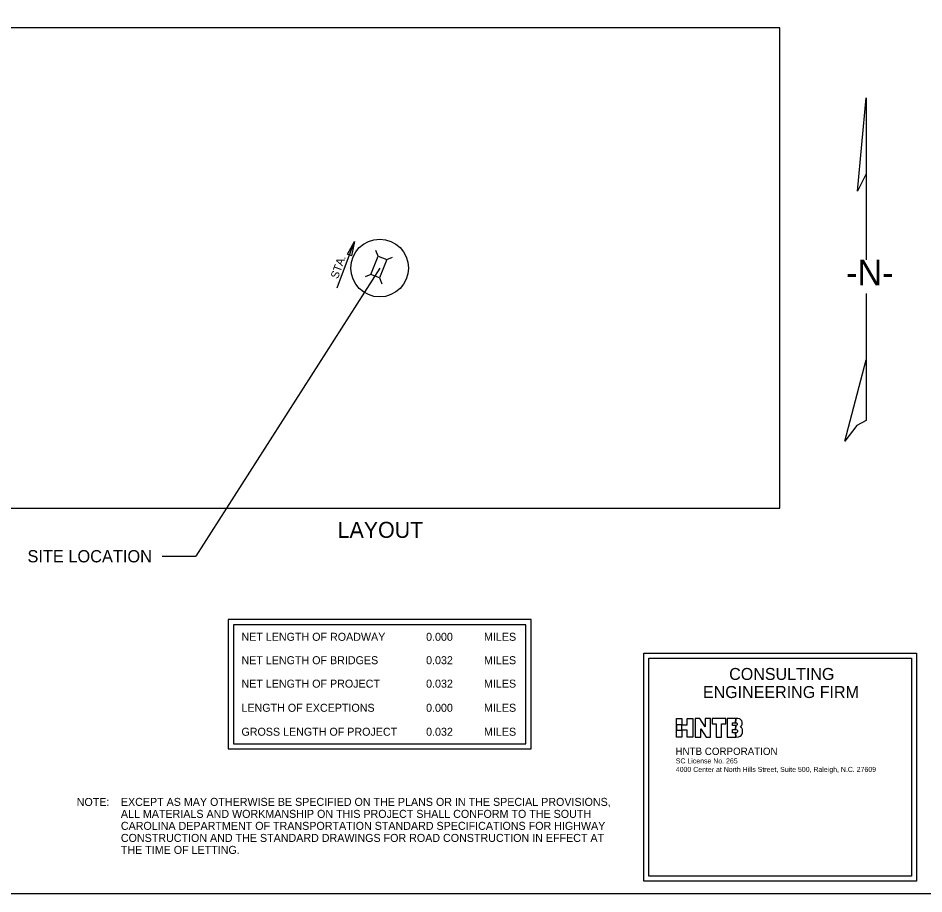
# Model space of a CAD drawing. Extents: x 0 to 4.05, y 0.02 to 4.32.
# Drawn here: x 1.008 to 2.188, y 0.042 to 1.182 of the extents above; entities that cross this region are included whole.
import ezdxf

# ---------------------------------------------------------------- set-up
doc = ezdxf.new("R2010")
doc.units = 0
for name, color, linetype in [('BR_AUTO DIMENSION', 7, 'Continuous'), ('BR_BORDER LINES', 7, 'Continuous'), ('BR_DETAILS', 7, 'Continuous'), ('BR_TEXT', 7, 'Continuous'), ('Default', 7, 'Continuous'), ('V7_23', 7, 'Continuous')]:
    doc.layers.add(name, color=color, linetype=linetype)

msp = doc.modelspace()

# ---------------------------------------------------------------- linework, layer by layer
at = {"layer": 'BR_AUTO DIMENSION'}
for p in [(1.4792, 0.8563), (1.1961, 0.4811)]:
    msp.add_line(p, (1.2399, 0.4811), dxfattribs=at)
msp.add_circle((1.4792, 0.8563), 0.0376, dxfattribs=at)
at = {"layer": 'BR_BORDER LINES'}
for points in [[(0.1667, 1.7917), (2.7917, 1.7917), (2.7917, 0.0417), (0.1667, 0.0417)], [(0.9583, 0.5438), (2, 0.5438), (2, 1.1688), (0.9583, 1.1688)]]:
    msp.add_lwpolyline(points, close=True, dxfattribs=at)
at = {"layer": 'BR_DETAILS'}
for p, q in [((1.8232, 0.3551), (2.1782, 0.3551)), ((1.8232, 0.0584), (1.8232, 0.3551)), ((2.1782, 0.3551), (2.1782, 0.0584)), ((1.8296, 0.3487), (2.1718, 0.3487)), ((1.8296, 0.0648), (1.8296, 0.3487)), ((2.1718, 0.3487), (2.1718, 0.0648)), ((2.1718, 0.0648), (1.8296, 0.0648)), ((2.1782, 0.0584), (1.8232, 0.0584))]:
    msp.add_line(p, q, dxfattribs=at)
at = {"layer": 'BR_TEXT'}
for p, q in [((1.4239, 0.8306), (1.4463, 0.8909)), ((1.4772, 0.8718), (1.4742, 0.8793)), ((1.4886, 0.8672), (1.496, 0.8706)), ((1.4676, 0.848), (1.4602, 0.8447)), ((1.479, 0.8434), (1.4821, 0.8359))]:
    msp.add_line(p, q, dxfattribs=at)
for points in [[(1.4372, 0.8743), (1.4463, 0.8909), (1.4424, 0.8724)], [(1.4772, 0.8718), (1.4886, 0.8672), (1.479, 0.8434), (1.4676, 0.848)], [(1.6763, 0.3987), (1.282, 0.3987), (1.282, 0.2303), (1.6763, 0.2303)], [(1.6696, 0.392), (1.2887, 0.392), (1.2887, 0.237), (1.6696, 0.237)]]:
    msp.add_lwpolyline(points, close=True, dxfattribs=at)
at = {"layer": 'Default'}
for p, q in [((2.1013, 0.9564), (2.1124, 1.0778)), ((2.1124, 1.0778), (2.1124, 0.979)), ((2.1124, 0.979), (2.1013, 0.9564)), ((2.1124, 0.979), (2.1124, 0.9105)), ((2.1124, 0.9105), (2.1124, 0.8668)), ((2.1124, 0.8232), (2.1124, 0.7369)), ((2.0849, 0.6311), (2.1124, 0.7369)), ((2.1124, 0.7369), (2.1124, 0.7238)), ((2.1124, 0.7238), (2.1124, 0.6577))]:
    msp.add_line(p, q, dxfattribs=at)
msp.add_lwpolyline([(2.1124, 0.6577), (2.1006, 0.6512), (2.0849, 0.6311)], dxfattribs=at)
at = {"layer": 'V7_23'}
for p, q in [((1.8655, 0.2458), (1.8655, 0.2698)), ((1.8655, 0.2698), (1.8726, 0.2698)), ((1.8726, 0.2617), (1.8658, 0.2617)), ((1.8658, 0.2617), (1.8658, 0.2546)), ((1.8726, 0.2698), (1.8726, 0.2617)), ((1.8726, 0.2546), (1.8726, 0.2617)), ((1.8726, 0.2617), (1.8797, 0.2617)), ((1.8797, 0.2617), (1.8797, 0.2698)), ((1.8797, 0.2698), (1.8868, 0.2698)), ((1.8868, 0.2698), (1.8868, 0.2458)), ((1.8959, 0.2698), (1.8901, 0.2698)), ((1.8901, 0.2698), (1.8901, 0.2458)), ((1.903, 0.2593), (1.8959, 0.2698)), ((1.91, 0.2698), (1.903, 0.2698)), ((1.903, 0.2698), (1.903, 0.2593)), ((1.91, 0.2458), (1.91, 0.2698)), ((1.912, 0.2698), (1.912, 0.2629)), ((1.9297, 0.2698), (1.912, 0.2698)), ((1.912, 0.2629), (1.9173, 0.2629)), ((1.9173, 0.2629), (1.9173, 0.2458)), ((1.9244, 0.2458), (1.9244, 0.2629)), ((1.9244, 0.2629), (1.9297, 0.2629)), ((1.9297, 0.2629), (1.9297, 0.2698)), ((1.9429, 0.2698), (1.9318, 0.2698)), ((1.9318, 0.2698), (1.9318, 0.2458)), ((1.9384, 0.2609), (1.9384, 0.2645)), ((1.9384, 0.2645), (1.9425, 0.2645)), ((1.9427, 0.2609), (1.9384, 0.2609)), ((1.9424, 0.2556), (1.9427, 0.2609)), ((1.9427, 0.2609), (1.9424, 0.2556)), ((1.9425, 0.2645), (1.9429, 0.2698)), ((1.9429, 0.2698), (1.9425, 0.2645)), ((1.8658, 0.2546), (1.8726, 0.2546)), ((1.8797, 0.2546), (1.8726, 0.2546)), ((1.8726, 0.2546), (1.8726, 0.2458)), ((1.8797, 0.2458), (1.8797, 0.2546)), ((1.8971, 0.2458), (1.8971, 0.2566)), ((1.8971, 0.2566), (1.9044, 0.2458)), ((1.9384, 0.2512), (1.9384, 0.2556)), ((1.9384, 0.2556), (1.9424, 0.2556)), ((1.9425, 0.2512), (1.9384, 0.2512)), ((1.9428, 0.2458), (1.9425, 0.2512)), ((1.9425, 0.2512), (1.9428, 0.2458)), ((1.8726, 0.2458), (1.8655, 0.2458)), ((1.8868, 0.2458), (1.8797, 0.2458)), ((1.8901, 0.2458), (1.8971, 0.2458)), ((1.9044, 0.2458), (1.91, 0.2458)), ((1.9173, 0.2458), (1.9244, 0.2458)), ((1.9318, 0.2458), (1.9428, 0.2458))]:
    msp.add_line(p, q, dxfattribs=at)
for points in [[(1.9425, 0.2645), (1.9444, 0.2645), (1.9446, 0.2632), (1.9446, 0.2627), (1.9446, 0.2621), (1.9442, 0.2609), (1.9427, 0.2609)], [(1.9491, 0.2588), (1.9504, 0.2599), (1.951, 0.2616), (1.951, 0.2628), (1.951, 0.2671), (1.9479, 0.2698), (1.9429, 0.2698), (1.9429, 0.2698), (1.9429, 0.2698), (1.9429, 0.2698)], [(1.9424, 0.2556), (1.9446, 0.2556), (1.945, 0.2544), (1.945, 0.2534), (1.945, 0.252), (1.9441, 0.2512), (1.9425, 0.2512)], [(1.9428, 0.2458), (1.9483, 0.2458), (1.9517, 0.2489), (1.9517, 0.2539), (1.9517, 0.2558), (1.9507, 0.2577), (1.9491, 0.2588)]]:
    msp.add_open_spline(points, degree=3, dxfattribs=at)

# ---------------------------------------------------------------- texts
at = {"layer": 'BR_TEXT'}
for s, height, rotation, p in [('STA.', 0.01042, 69.6593, (1.4246, 0.8416)), ('SITE LOCATION ', 0.015922, 360, (1.0206, 0.4732)), ('CONSULTING', 0.01563, 0, (1.9342, 0.3201)), ('ENGINEERING FIRM', 0.015625, 0, (1.9, 0.2966))]:
    msp.add_text(s, height=height, rotation=rotation, dxfattribs=at).set_placement(p)
for s, height, p in [('HNTB CORPORATION', 0.009516, (1.8643, 0.2225)), ('SC License No. 265', 0.006558, (1.8647, 0.2115)), ('4000 Center at North Hills Street, Suite 500, Raleigh, N.C. 27609', 0.006558, (1.8647, 0.2004))]:
    msp.add_text(s, height=height, dxfattribs=at).set_placement(p)
at = {"layer": 'Default'}
for s, height, p in [('-N-', 0.03333, (2.0864, 0.8337)), ('LAYOUT', 0.02083, (1.4244, 0.5051)), ('NET LENGTH OF ROADWAY', 0.010417, (1.2992, 0.3711)), ('0.000', 0.01042, (1.5396, 0.3711)), ('MILES', 0.01042, (1.615, 0.3711)), ('NET LENGTH OF BRIDGES', 0.010417, (1.2992, 0.3406)), ('0.032', 0.01042, (1.5396, 0.3406)), ('MILES', 0.01042, (1.615, 0.3406)), ('NET LENGTH OF PROJECT', 0.010417, (1.2992, 0.3101)), ('0.032', 0.01042, (1.5396, 0.3101)), ('MILES', 0.01042, (1.615, 0.3101)), ('LENGTH OF EXCEPTIONS', 0.010417, (1.2992, 0.2787)), ('0.000', 0.01042, (1.5396, 0.2787)), ('MILES', 0.01042, (1.615, 0.2787)), ('GROSS LENGTH OF PROJECT', 0.010417, (1.2992, 0.2475)), ('0.032', 0.01042, (1.5396, 0.2475)), ('MILES', 0.01042, (1.615, 0.2475)), ('NOTE:', 0.01042, (1.0847, 0.1561)), ('EXCEPT AS MAY OTHERWISE BE SPECIFIED ON THE PLANS OR IN THE SPECIAL PROVISIONS, ', 0.010417, (1.1422, 0.1562)), ('ALL MATERIALS AND WORKMANSHIP ON THIS PROJECT SHALL CONFORM TO THE SOUTH ', 0.010417, (1.1422, 0.1406)), ('CAROLINA DEPARTMENT OF TRANSPORTATION STANDARD SPECIFICATIONS FOR HIGHWAY ', 0.010417, (1.1422, 0.125)), ('CONSTRUCTION AND THE STANDARD DRAWINGS FOR ROAD CONSTRUCTION IN EFFECT AT ', 0.010417, (1.1422, 0.1093)), ('THE TIME OF LETTING.', 0.010417, (1.1422, 0.0937))]:
    msp.add_text(s, height=height, dxfattribs=at).set_placement(p)

doc.saveas('drawing.dxf')
